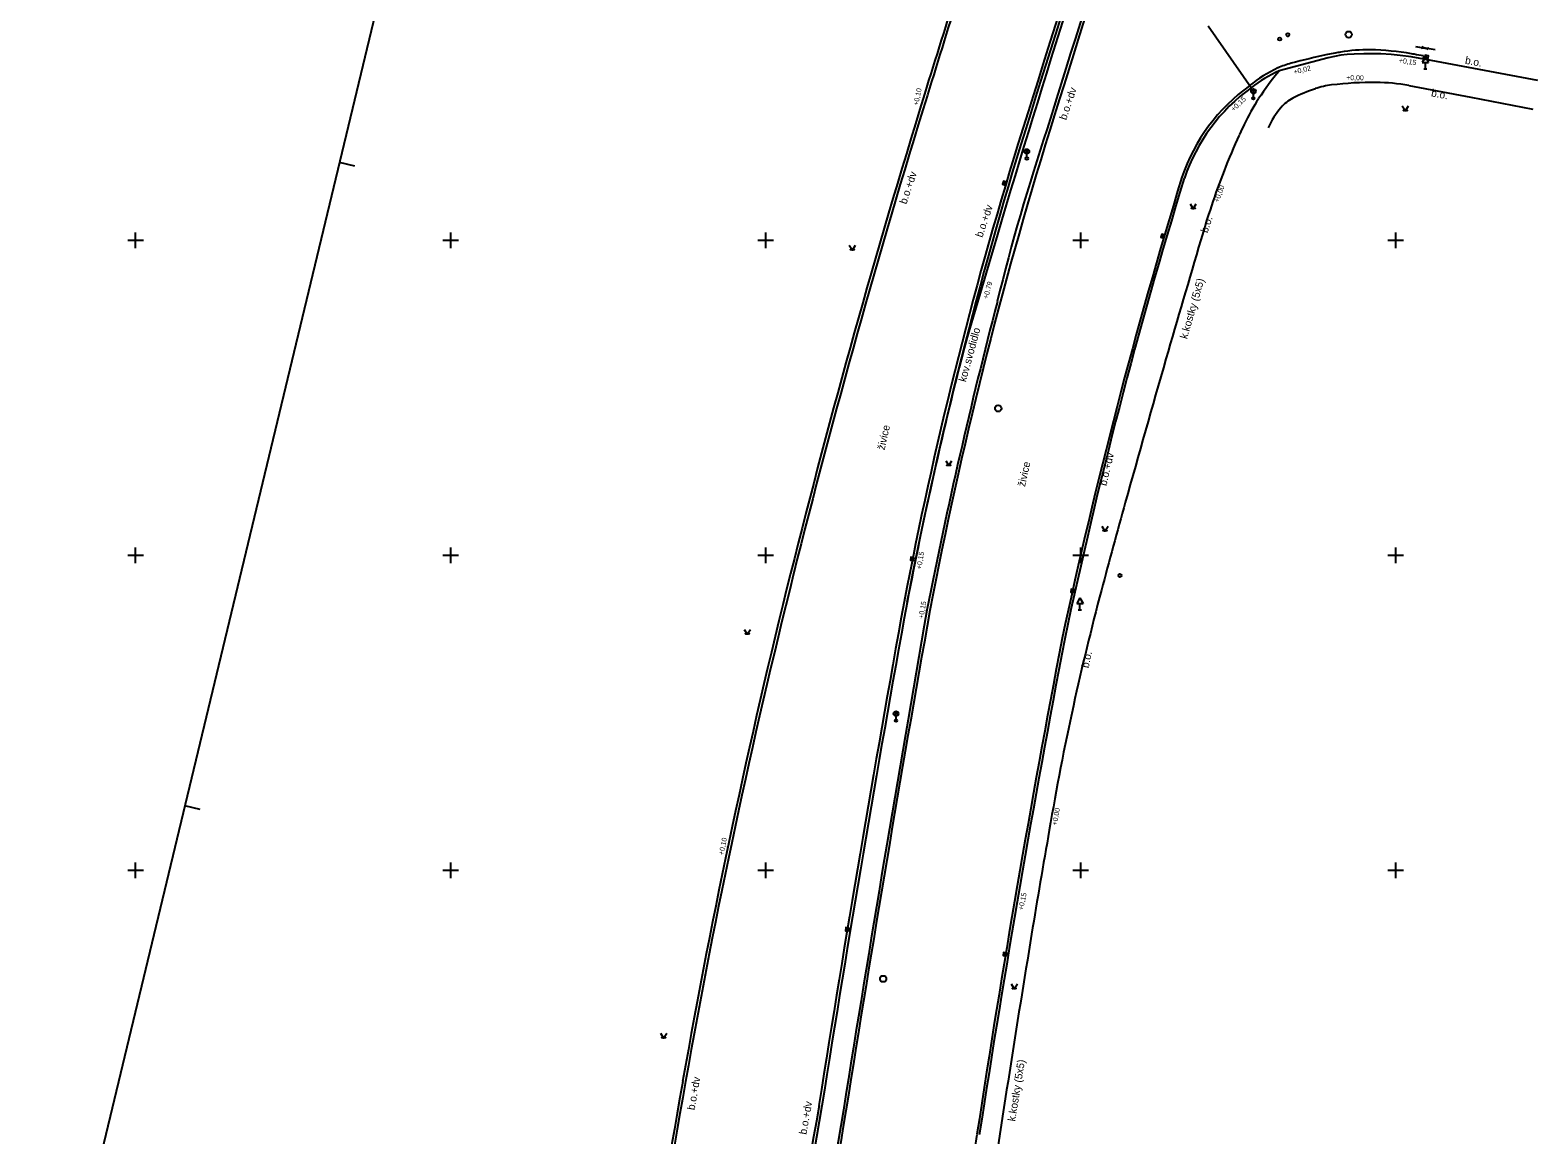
# Model space of a CAD drawing. Extents: x -599151 to -598424, y -1163476 to -1161924.
# Drawn here: x -598708.4 to -598588.7, y -1162296 to -1162208.3 of the extents above; entities that cross this region are included whole.
import ezdxf

# ---------------------------------------------------------------- set-up
doc = ezdxf.new("R2010")
doc.units = 0
for name, color, linetype in [('Vrstva 1', 7, 'Continuous'), ('Vrstva 14', 7, 'Continuous'), ('Vrstva 19', 7, 'Continuous'), ('Vrstva 21', 7, 'Continuous'), ('Vrstva 24', 7, 'Continuous'), ('Vrstva 25', 7, 'Continuous'), ('Vrstva 29', 7, 'Continuous'), ('Vrstva 49', 7, 'Continuous'), ('Vrstva 50', 7, 'Continuous'), ('Vrstva 62', 7, 'Continuous'), ('Vrstva 63', 7, 'Continuous'), ('Vrstva 7', 7, 'Continuous')]:
    doc.layers.add(name, color=color, linetype=linetype)

msp = doc.modelspace()

# ---------------------------------------------------------------- linework, layer by layer
at = {"layer": 'Vrstva 1'}
for p, q in [((-598622.44, -1161963.62), (-598708.37, -1162320.93)), ((-598682.6, -1162219.13), (-598683.82, -1162218.84)), ((-598694.88, -1162270.18), (-598696.09, -1162269.88))]:
    msp.add_line(p, q, dxfattribs=at)
at = {"layer": 'Vrstva 14'}
for points in [[(-598599.49, -1162214.35), (-598599.24, -1162214.73), (-598598.99, -1162214.35)], [(-598616.33, -1162222.12), (-598616.08, -1162222.5), (-598615.83, -1162222.12)], [(-598643.37, -1162225.4), (-598643.12, -1162225.78), (-598642.87, -1162225.4)], [(-598635.72, -1162242.51), (-598635.47, -1162242.89), (-598635.22, -1162242.51)], [(-598623.33, -1162247.7), (-598623.08, -1162248.08), (-598622.83, -1162247.7)], [(-598651.72, -1162255.88), (-598651.47, -1162256.25), (-598651.22, -1162255.88)], [(-598630.53, -1162284.02), (-598630.28, -1162284.4), (-598630.03, -1162284.02)], [(-598658.35, -1162287.93), (-598658.1, -1162288.31), (-598657.85, -1162287.93)]]:
    msp.add_lwpolyline(points, dxfattribs=at)
for centre in [(-598599.36, -1162214.7), (-598599.11, -1162214.7), (-598616.2, -1162222.47), (-598615.95, -1162222.47), (-598643.25, -1162225.75), (-598643, -1162225.75), (-598635.6, -1162242.86), (-598635.35, -1162242.86), (-598623.21, -1162248.05), (-598622.96, -1162248.05), (-598651.59, -1162256.23), (-598651.34, -1162256.23), (-598630.41, -1162284.37), (-598630.16, -1162284.37), (-598658.22, -1162288.28), (-598657.97, -1162288.28)]:
    msp.add_circle(centre, 0.025, dxfattribs=at)
at = {"layer": 'Vrstva 19'}
for p, q in [((-598597.65, -1162210.46), (-598597.9, -1162210.89)), ((-598597.65, -1162210.46), (-598597.4, -1162210.89)), ((-598597.9, -1162210.89), (-598597.4, -1162210.89)), ((-598597.78, -1162211.39), (-598597.53, -1162211.39)), ((-598597.65, -1162211.39), (-598597.65, -1162210.89)), ((-598625.07, -1162253.39), (-598625.32, -1162253.82)), ((-598625.07, -1162253.39), (-598624.82, -1162253.82)), ((-598625.32, -1162253.82), (-598624.82, -1162253.82)), ((-598625.2, -1162254.32), (-598624.95, -1162254.32)), ((-598625.07, -1162254.32), (-598625.07, -1162253.82))]:
    msp.add_line(p, q, dxfattribs=at)
at = {"layer": 'Vrstva 21'}
for centre, radius, start, end in [((-597493.02, -1162563.38), 1187.94, 162.01983, 163.89601), ((-598313.39, -1162315.99), 331.29, 165.6485, 169.1719), ((-596899.44, -1162568.25), 1767.55, 169.75093, 171.06399), ((-597963.69, -1162412.59), 692.14, 170.10853, 173.4421)]:
    msp.add_arc(centre, radius, start, end, dxfattribs=at)
at = {"layer": 'Vrstva 24'}
for centre in [(-598609.21, -1162209.04), (-598608.57, -1162208.7), (-598621.89, -1162251.61)]:
    msp.add_circle(centre, 0.125, dxfattribs=at)
at = {"layer": 'Vrstva 25'}
for p, q in [((-598597.68, -1162210.45), (-598597.44, -1162210.51)), ((-598631.09, -1162220.6), (-598631.01, -1162220.36)), ((-598618.53, -1162224.81), (-598618.45, -1162224.57)), ((-598638.4, -1162250.41), (-598638.36, -1162250.17)), ((-598625.68, -1162252.94), (-598625.64, -1162252.7)), ((-598643.56, -1162279.81), (-598643.52, -1162279.57)), ((-598631.04, -1162281.79), (-598631, -1162281.55))]:
    msp.add_line(p, q, dxfattribs=at)
for points in [[(-598597.71, -1162210.58), (-598597.46, -1162210.63), (-598597.41, -1162210.38), (-598597.66, -1162210.33)], [(-598630.97, -1162220.64), (-598630.89, -1162220.4), (-598631.13, -1162220.32), (-598631.21, -1162220.56)], [(-598618.41, -1162224.85), (-598618.33, -1162224.61), (-598618.57, -1162224.53), (-598618.65, -1162224.77)], [(-598638.28, -1162250.43), (-598638.24, -1162250.19), (-598638.48, -1162250.15), (-598638.52, -1162250.39)], [(-598625.56, -1162252.96), (-598625.52, -1162252.72), (-598625.76, -1162252.68), (-598625.8, -1162252.92)], [(-598643.44, -1162279.83), (-598643.4, -1162279.59), (-598643.64, -1162279.55), (-598643.68, -1162279.79)], [(-598630.92, -1162281.81), (-598630.88, -1162281.57), (-598631.12, -1162281.53), (-598631.16, -1162281.77)]]:
    msp.add_lwpolyline(points, close=True, dxfattribs=at)
for centre in [(-598603.74, -1162208.68), (-598631.55, -1162238.35), (-598640.68, -1162283.61)]:
    msp.add_circle(centre, 0.25, dxfattribs=at)
at = {"layer": 'Vrstva 29'}
for p, q in [((-598611.43, -1162213.31), (-598611.17, -1162213.04)), ((-598611.16, -1162213.31), (-598611.43, -1162213.04)), ((-598611.3, -1162213.64), (-598611.3, -1162213.36)), ((-598629.41, -1162218.09), (-598629.15, -1162217.82)), ((-598629.14, -1162218.09), (-598629.41, -1162217.82)), ((-598629.28, -1162218.42), (-598629.28, -1162218.15)), ((-598639.52, -1162262.7), (-598639.79, -1162262.43)), ((-598639.79, -1162262.7), (-598639.53, -1162262.44)), ((-598639.66, -1162263.03), (-598639.66, -1162262.76))]:
    msp.add_line(p, q, dxfattribs=at)
for centre, radius in [((-598611.3, -1162213.18), 0.188), ((-598611.3, -1162213.74), 0.1), ((-598629.28, -1162217.96), 0.188), ((-598629.28, -1162218.52), 0.1), ((-598639.66, -1162262.57), 0.188), ((-598639.66, -1162263.13), 0.1)]:
    msp.add_circle(centre, radius, dxfattribs=at)
at = {"layer": 'Vrstva 49'}
for p, q in [((-598598.45, -1162209.62), (-598597.67, -1162209.76)), ((-598597.67, -1162209.76), (-598597.95, -1162209.79)), ((-598597.93, -1162209.64), (-598597.67, -1162209.76)), ((-598597.67, -1162209.76), (-598597.39, -1162209.74)), ((-598596.89, -1162209.9), (-598597.67, -1162209.76)), ((-598597.42, -1162209.88), (-598597.67, -1162209.76))]:
    msp.add_line(p, q, dxfattribs=at)
at = {"layer": 'Vrstva 62'}
for p, q in [((-598700, -1162225.62), (-598700, -1162224.38)), ((-598675, -1162225.62), (-598675, -1162224.38)), ((-598650, -1162225.62), (-598650, -1162224.38)), ((-598625, -1162225.62), (-598625, -1162224.38)), ((-598600, -1162225.62), (-598600, -1162224.38)), ((-598700.62, -1162225), (-598699.38, -1162225)), ((-598675.62, -1162225), (-598674.38, -1162225)), ((-598650.62, -1162225), (-598649.38, -1162225)), ((-598625.62, -1162225), (-598624.38, -1162225)), ((-598600.62, -1162225), (-598599.38, -1162225)), ((-598700.62, -1162250), (-598699.38, -1162250)), ((-598700, -1162250.62), (-598700, -1162249.38)), ((-598675.62, -1162250), (-598674.38, -1162250)), ((-598675, -1162250.62), (-598675, -1162249.38)), ((-598650.62, -1162250), (-598649.38, -1162250)), ((-598650, -1162250.62), (-598650, -1162249.38)), ((-598625.62, -1162250), (-598624.38, -1162250)), ((-598625, -1162250.62), (-598625, -1162249.38)), ((-598600.62, -1162250), (-598599.38, -1162250)), ((-598600, -1162250.62), (-598600, -1162249.38)), ((-598700.62, -1162275), (-598699.38, -1162275)), ((-598700, -1162275.62), (-598700, -1162274.38)), ((-598675.62, -1162275), (-598674.38, -1162275)), ((-598675, -1162275.62), (-598675, -1162274.38)), ((-598650.62, -1162275), (-598649.38, -1162275)), ((-598650, -1162275.62), (-598650, -1162274.38)), ((-598625.62, -1162275), (-598624.38, -1162275)), ((-598625, -1162275.62), (-598625, -1162274.38)), ((-598600.62, -1162275), (-598599.38, -1162275)), ((-598600, -1162275.62), (-598600, -1162274.38))]:
    msp.add_line(p, q, dxfattribs=at)
at = {"layer": 'Vrstva 63'}
msp.add_lwpolyline([(-598611.49, -1162212.91), (-598614.89, -1162208.02)], dxfattribs=at)
for centre, radius, start, end in [((-597355.61, -1162612.89), 1334.11, 160.9522, 162.75599), ((-597604.98, -1162529.48), 1069.6, 160.81129, 162.96716), ((-597837.75, -1162459.16), 836.56, 161.68884, 162.91678), ((-598602.92, -1162224.77), 14.63, 125.8309, 161.2532), ((-597951.44, -1162425.65), 718.04, 162.80781, 165.95912), ((-598465.62, -1162270.43), 170.89, 161.4866, 166.2694), ((-598289.2, -1162321.39), 356.08, 163.0192, 169.0492), ((-598213.57, -1162344.24), 421.9, 162.8831, 168.0143), ((-598229.78, -1162334.51), 415.24, 165.4044, 168.8697), ((-598063.06, -1162396.7), 602.74, 166.05449, 169.97347), ((-596899.44, -1162568.25), 1767.55, 169.75093, 171.06399), ((-595842.24, -1162741.63), 2837.13, 170.11028, 170.92294), ((-597501, -1162470.73), 1145.46, 169.22743, 171.22531), ((-598078.54, -1162394.97), 587.19, 169.87698, 173.86679), ((-597963.69, -1162412.59), 692.14, 170.10853, 173.4421), ((-597911.96, -1162421.25), 742.85, 170.13971, 173.22764)]:
    msp.add_arc(centre, radius, start, end, dxfattribs=at)
at = {"layer": 'Vrstva 7'}
msp.add_line((-598597.8, -1162210.38), (-598597.84, -1162210.62), dxfattribs=at)
for points in [[(-598588.73, -1162212.34), (-598597.19, -1162210.74), (-598598.79, -1162210.46), (-598599.65, -1162210.34), (-598600.37, -1162210.27), (-598601.18, -1162210.22), (-598601.91, -1162210.2), (-598602.54, -1162210.2), (-598603.31, -1162210.23), (-598603.86, -1162210.27), (-598604.35, -1162210.32), (-598605.37, -1162210.52), (-598609.25, -1162211.57)], [(-598598.97, -1162212.73), (-598594.05, -1162213.66), (-598589.13, -1162214.59)]]:
    msp.add_lwpolyline(points, dxfattribs=at)
for centre, radius, start, end in [((-597393.9, -1162600.63), 1294.13, 160.91221, 162.77046), ((-597355.61, -1162612.89), 1334.11, 160.9522, 162.75599), ((-597604.98, -1162529.48), 1069.6, 160.81126, 162.96716), ((-597520.77, -1162556.75), 1157.87, 160.90706, 162.89842), ((-597837.75, -1162459.16), 836.56, 161.68884, 162.91678), ((-597837.2, -1162457.35), 836.31, 161.81715, 163.04586), ((-598594.64, -1162261.84), 52.68, 101.8075, 105.0419), ((-598595.4, -1162258.23), 48.99, 101.0937, 101.8075), ((-598600.02, -1162234.63), 24.94, 100.0908, 101.0937), ((-598602.31, -1162221.77), 11.87, 88.5576, 100.0908), ((-598602.59, -1162232.58), 22.7, 80.2647, 88.5576), ((-598610.85, -1162280.73), 71.55, 80.1054, 80.2647), ((-599232.54, -1165844.84), 3689.47, 80.0935, 80.10541), ((-598604.56, -1162221.55), 11.29, 115.1648, 128.6875), ((-598604.73, -1162221.66), 11.06, 114.1104, 127.6665), ((-598591.86, -1162226.26), 22.76, 139.7702, 146.7134), ((-598608.48, -1162213.27), 2.12, 114.1451, 114.5153), ((-598606.53, -1162217.61), 6.88, 105.0419, 114.1451), ((-598602.92, -1162224.77), 14.84, 125.8309, 161.1964), ((-598602.92, -1162224.77), 14.63, 125.8309, 161.2532), ((-598601.92, -1162226.08), 13.84, 108.8247, 116.8611), ((-598604.3, -1162219.1), 6.47, 97.0563, 108.8247), ((-598601.78, -1162239.43), 26.95, 89.5319, 97.0563), ((-598601.68, -1162227.06), 14.58, 79.296, 89.5319), ((-597951.44, -1162425.65), 718.04, 162.80781, 165.95912), ((-597939.35, -1162428.94), 730.33, 162.84136, 165.9379), ((-598597.56, -1162222.56), 15.96, 146.5961, 155.0618), ((-598606.81, -1162216.42), 3.01, 116.8611, 140.1944), ((-598603.68, -1162219.03), 7.09, 140.1944, 155.348), ((-598295.43, -1162319.43), 347.68, 162.7388, 169.2171), ((-598465.62, -1162270.43), 170.89, 161.4866, 166.2694), ((-598605.75, -1162219.68), 7.34, 154.867, 155.6273), ((-598157.92, -1162433.03), 503.38, 154.4386, 154.5314), ((-598309.58, -1162316.31), 335.33, 162.8289, 169.2394), ((-598289.2, -1162321.39), 356.08, 163.0193, 169.0492), ((-598559.29, -1162240.73), 58.34, 155.6273, 158.6562), ((-598197.72, -1162348.46), 438.49, 162.9632, 167.9059), ((-598213.57, -1162344.24), 421.9, 162.8831, 168.0143), ((-598563.47, -1162239.09), 53.85, 158.6562, 161.8092), ((-598521.37, -1162252.93), 98.17, 161.8092, 163.4523), ((-597021.07, -1162697.72), 1663.01, 163.48464, 163.82378), ((-598229.78, -1162334.51), 415.24, 165.4044, 168.8697), ((-597237.98, -1162631.56), 1436.26, 163.94786, 164.42017), ((-598156.5, -1162375.86), 482.81, 164.3734, 165.2301), ((-598063.06, -1162396.7), 602.74, 166.05449, 169.97347), ((-598084.24, -1162392.58), 580.94, 165.94389, 170.00651), ((-598408.8, -1162309.64), 221.97, 165.1539, 167.5933), ((-596918.95, -1162565.23), 1748.05, 169.73402, 171.06243), ((-596899.44, -1162568.25), 1767.55, 169.75092, 171.06398), ((-595842.24, -1162741.63), 2837.13, 170.11028, 170.92294), ((-596584.71, -1162618.99), 2084.4, 169.92579, 171.0326), ((-597580.45, -1162456.5), 1064.96, 169.18028, 171.32901), ((-597501, -1162470.73), 1145.46, 169.22743, 171.22531), ((-598433.13, -1162304.4), 197.08, 167.5615, 170.4822), ((-597719.01, -1162431.07), 922.34, 170.05697, 170.57761), ((-597401.73, -1162482.84), 1243.81, 170.6179, 171.12921), ((-598078.54, -1162394.97), 587.19, 169.87697, 173.86679), ((-598051.2, -1162398.68), 614.54, 169.98126, 173.7942), ((-595088.62, -1162847.57), 3585.5, 171.07055, 171.25097), ((-598011.35, -1162405.68), 644.23, 169.98614, 173.56856), ((-597963.69, -1162412.59), 692.14, 170.10853, 173.4421), ((-597911.96, -1162421.25), 742.85, 170.13971, 173.22764), ((-597873.54, -1162427.08), 781.49, 170.20184, 173.13718), ((-597790.29, -1162439.78), 855.13, 170.31711, 172.96797)]:
    msp.add_arc(centre, radius, start, end, dxfattribs=at)

# ---------------------------------------------------------------- texts
at = {"layer": 'Vrstva 49'}
for s, height, rotation, p in [('b.o.', 0.6, 349.2848, (-598594.54, -1162210.99)), ('b.o.+dv', 0.6, 71.463, (-598626.16, -1162215.51)), ('b.o.', 0.6, 349.2848, (-598597.23, -1162213.58)), ('b.o.+dv', 0.6, 71.463, (-598638.84, -1162222.19)), ('b.o.+dv', 0.6, 71.463, (-598632.81, -1162224.83)), ('b.o.', 0.6, 71.4051, (-598614.95, -1162224.47)), ('k.kostky (5x5)', 0.6, 73.7462, (-598616.57, -1162232.88)), ('kov.svodidlo', 0.5999, 74.7834, (-598634.12, -1162236.29)), ('živice', 0.6, 77.3672, (-598640.57, -1162241.69)), ('živice', 0.6, 77.3672, (-598629.43, -1162244.6)), ('b.o.+dv', 0.6, 76.5373, (-598622.97, -1162244.53)), ('b.o.', 0.6, 77.7387, (-598624.38, -1162258.99)), ('k.kostky (5x5)', 0.6, 80.7921, (-598630.21, -1162294.95)), ('b.o.+dv', 0.6, 79.9473, (-598655.65, -1162294.06)), ('b.o.+dv', 0.6, 79.9473, (-598646.77, -1162296))]:
    msp.add_text(s, height=height, rotation=rotation, dxfattribs=at).set_placement(p)
at = {"layer": 'Vrstva 50'}
for s, rotation, p in [('+0,15', 351.603, (-598599.78, -1162210.91)), ('+0,02', 13.7472, (-598608.06, -1162211.85)), ('+0,10', 78.0993, (-598637.91, -1162214.35)), ('+0,00', 359.5319, (-598603.94, -1162212.3)), ('+0,15', 43.9315, (-598612.86, -1162214.82)), ('+0,00', 69.5933, (-598614.07, -1162222.04)), ('+0.79', 74.9646, (-598632.37, -1162229.69)), ('+0,15', 80.3744, (-598637.66, -1162251.13)), ('+0,15', 80.3744, (-598637.49, -1162255.06)), ('+0,00', 79.552, (-598626.9, -1162271.46)), ('+0,10', 78.0993, (-598653.35, -1162273.82)), ('+0,15', 78.0831, (-598629.58, -1162278.19))]:
    msp.add_text(s, height=0.4, rotation=rotation, dxfattribs=at).set_placement(p)

doc.saveas('drawing.dxf')
